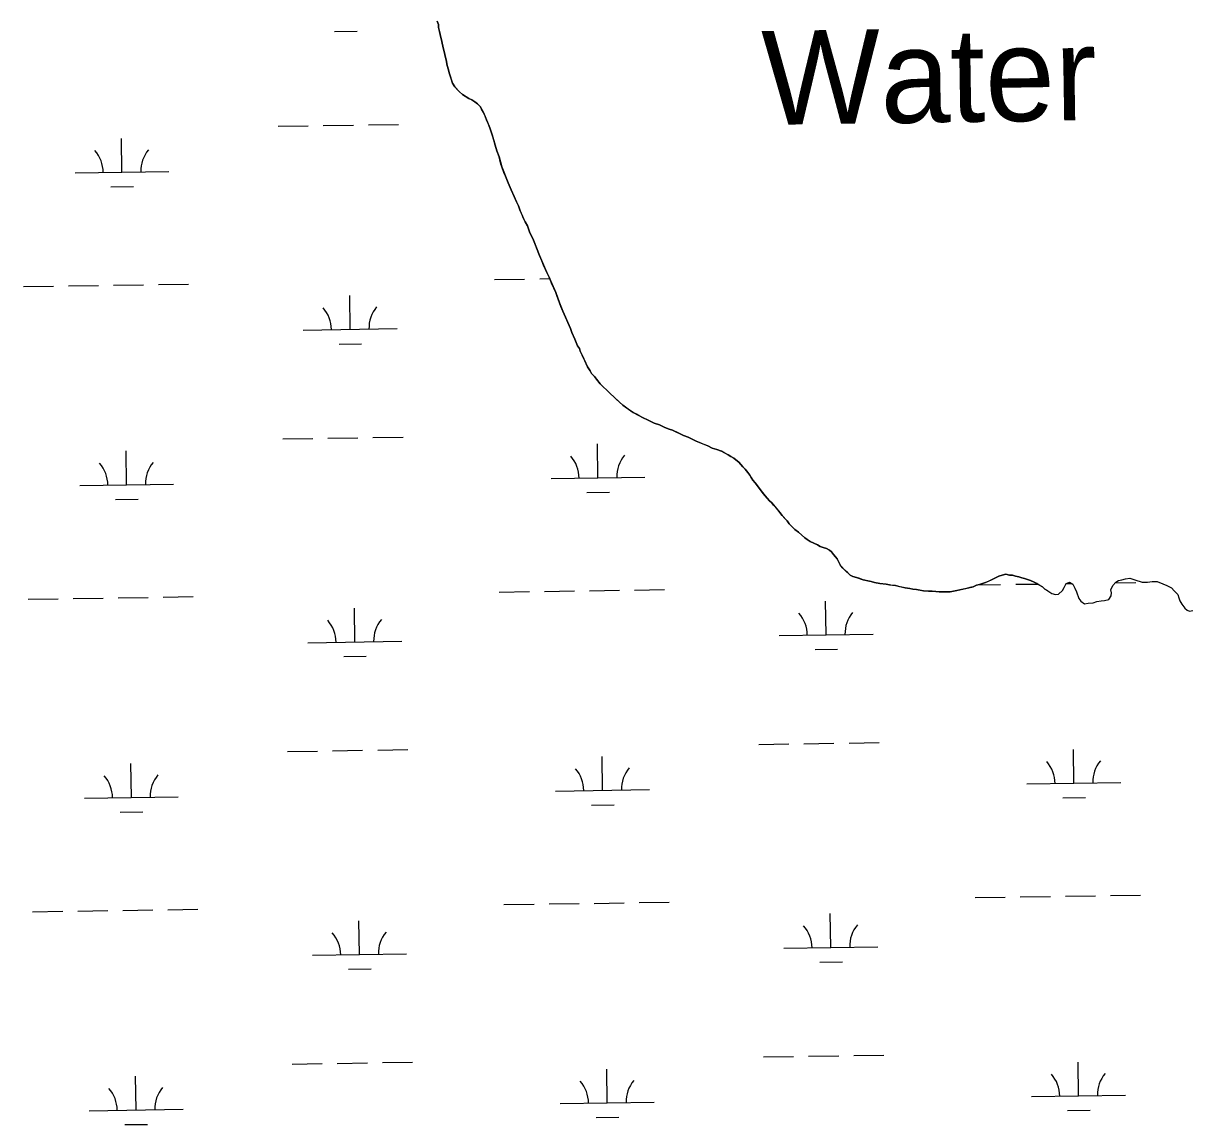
# Model space of a CAD drawing. Extents: x 3807117 to 3845308, y 337856 to 363736.
# Drawn here: x 3840561 to 3841805, y 350277 to 351449 of the extents above; entities that cross this region are included whole.
import ezdxf

# ---------------------------------------------------------------- set-up
doc = ezdxf.new("R2010")
doc.units = 0
for name, color, linetype in [('V-RIVR-IDEN', 7, 'Continuous'), ('V-TOPO-SHOR', 7, 'Continuous'), ('V-WETL-SWMP', 7, 'Continuous')]:
    doc.layers.add(name, color=color, linetype=linetype)

msp = doc.modelspace()

# ---------------------------------------------------------------- linework, layer by layer
at = {"layer": 'V-TOPO-SHOR'}
for p, q in [((3841668.1, 350845.4), (3841670, 350848.6)), ((3841670, 350848.6), (3841672, 350852.6)), ((3841672, 350852.6), (3841675.5, 350854.2)), ((3841675.5, 350854.2), (3841679.1, 350852.2)), ((3841679.1, 350852.2), (3841681.1, 350847.9)), ((3841681.1, 350847.9), (3841683.1, 350844)), ((3841719.6, 350845.9), (3841721.5, 350850.7)), ((3841721.5, 350850.7), (3841724.7, 350854.2)), ((3841724.7, 350854.2), (3841727.8, 350855.9)), ((3841727.8, 350855.9), (3841731.4, 350856.7)), ((3841731.4, 350856.7), (3841735.3, 350857.9)), ((3841735.3, 350857.9), (3841739.7, 350858.3)), ((3841739.7, 350858.3), (3841744.9, 350856.8)), ((3841744.9, 350856.8), (3841752.8, 350854.1)), ((3841752.8, 350854.1), (3841758.4, 350854.2)), ((3841758.4, 350854.2), (3841763.5, 350855)), ((3841763.5, 350855), (3841768.7, 350855)), ((3841768.7, 350855), (3841775, 350852.3)), ((3841775, 350852.3), (3841779, 350850.8)), ((3841779, 350850.8), (3841784.2, 350848)), ((3841784.2, 350848), (3841787, 350844.9)), ((3841651.5, 350845.6), (3841652.6, 350844.9)), ((3841652.6, 350844.9), (3841656.6, 350842.1)), ((3841656.6, 350842.1), (3841660.6, 350841)), ((3841660.6, 350841), (3841663.7, 350841.4)), ((3841663.7, 350841.4), (3841668.1, 350845.4)), ((3841683.1, 350844), (3841685.6, 350836.8)), ((3841685.6, 350836.8), (3841687.6, 350834.1)), ((3841687.6, 350834.1), (3841691.6, 350831)), ((3841704.6, 350833.5), (3841709.4, 350834.3)), ((3841709.4, 350834.3), (3841712.6, 350834.7)), ((3841712.6, 350834.7), (3841717.3, 350835.9)), ((3841717.3, 350835.9), (3841719.7, 350839.5)), ((3841720.4, 350842.7), (3841719.6, 350845.9)), ((3841719.7, 350839.5), (3841720.4, 350842.7)), ((3841787, 350844.9), (3841791, 350841)), ((3841791, 350841), (3841791.8, 350837.4)), ((3841791.8, 350837.4), (3841793, 350834.3)), ((3841793, 350834.3), (3841795.1, 350830.7)), ((3841691.6, 350831), (3841695.5, 350831.8)), ((3841695.5, 350831.8), (3841700.7, 350832.2)), ((3841700.7, 350832.2), (3841704.6, 350833.5)), ((3841795.1, 350830.7), (3841798.3, 350826.4)), ((3841798.3, 350826.4), (3841800.7, 350824.4)), ((3841800.7, 350824.4), (3841803.4, 350823.3)), ((3841803.4, 350823.3), (3841807, 350824.1))]:
    msp.add_line(p, q, dxfattribs=at)
for points in [[(3841058.4, 351337.6), (3841056.3, 351342.3), (3841054.7, 351346.3), (3841053.1, 351350.2), (3841051.5, 351354.1), (3841049.5, 351357.6), (3841047.9, 351360.4), (3841045.1, 351363.1), (3841042.4, 351365.4), (3841039.2, 351367.4), (3841035.7, 351368.9), (3841032.9, 351370.8), (3841029.3, 351373.2), (3841025.8, 351375.9), (3841023.8, 351378.2), (3841021, 351381.3), (3841018.6, 351385.3), (3841017, 351390), (3841015.4, 351395.1), (3841013.7, 351400.5), (3841012.5, 351405.6), (3841012.1, 351408.8), (3841010.9, 351412.7), (3841009.6, 351419), (3841008.4, 351422.9), (3841007.2, 351429.6), (3841005.2, 351437), (3841004.7, 351440.2), (3841003.5, 351444.5), (3841003.5, 351447.6), (3841002.3, 351451.2)], [(3841336.6, 350965.5), (3841335, 350968.2), (3841333, 350970.9), (3841330.2, 350974.4), (3841327.8, 350976.8), (3841325.4, 350979.5), (3841323.5, 350981.9), (3841320.3, 350984.2), (3841317.9, 350986.1), (3841314.7, 350988.1), (3841312, 350989.6), (3841308.4, 350991.6), (3841304.9, 350993.5), (3841300.1, 350995.4), (3841295, 350996.9), (3841290.3, 350999.2), (3841285.5, 351001.2), (3841281.6, 351002.7), (3841278, 351004.2), (3841272.9, 351006.6), (3841269.3, 351008.5), (3841264.6, 351010.4), (3841258.7, 351013.1), (3841252.8, 351015.8), (3841249.2, 351017), (3841244.5, 351018.9), (3841238.9, 351021.6), (3841233.4, 351023.5), (3841229.1, 351025.4), (3841226.3, 351027), (3841221.6, 351028.9), (3841218, 351030.8), (3841214.5, 351032.8), (3841210.9, 351034.7), (3841208.1, 351036.6), (3841204.2, 351039.4), (3841199.8, 351042.5), (3841196.3, 351045.6), (3841193.1, 351048.7), (3841190.7, 351051), (3841186.3, 351054.9), (3841183.2, 351058), (3841178.4, 351062.3), (3841175.6, 351065.1), (3841171.7, 351070.1), (3841169.7, 351072.9), (3841166.5, 351076.4), (3841164.9, 351079.1), (3841162.1, 351083.4), (3841159.3, 351089.7), (3841156.5, 351095.9), (3841154.5, 351099.9), (3841153.7, 351103), (3841151.7, 351105.7), (3841148.9, 351112.8), (3841145.7, 351119.8), (3841144, 351124.1), (3841141.2, 351130.4), (3841138.8, 351136.3), (3841136, 351142.5), (3841134, 351147.6), (3841132.4, 351151.6), (3841129.6, 351159.4), (3841128.4, 351162.5), (3841126.4, 351167.2), (3841124.7, 351170.7), (3841122.7, 351175.4), (3841121.5, 351178.6), (3841119.1, 351183.7), (3841117.5, 351186.8), (3841115.5, 351191.5), (3841113.5, 351196.2), (3841111.1, 351201.7), (3841107.9, 351209.9), (3841106.7, 351213), (3841104.7, 351218.1), (3841102.6, 351222.8), (3841101, 351226), (3841099.4, 351230.3), (3841098.2, 351233.4), (3841095.8, 351237.7), (3841094.2, 351241.2), (3841092.2, 351245.9), (3841090.6, 351249.5), (3841088.6, 351254.6), (3841086.6, 351258.9), (3841084.2, 351264.7), (3841081, 351271.8), (3841077.8, 351279.2), (3841074.9, 351286.3), (3841073.3, 351290.2), (3841070.9, 351296.1), (3841070.1, 351299.2), (3841068.9, 351303.5), (3841068.1, 351306.7), (3841065.7, 351313.3), (3841064, 351319.2), (3841062.4, 351324.7), (3841060.8, 351330.2), (3841059.2, 351334.5), (3841058.4, 351337.6)], [(3841652.6, 350844.9), (3841649.4, 350846.8), (3841646.7, 350849.1), (3841643.9, 350850.7), (3841640.7, 350852.6), (3841638, 350854.2), (3841634, 350856.1), (3841630.9, 350856.9), (3841627.7, 350858), (3841624.6, 350858.8), (3841621.4, 350859.9), (3841617.9, 350860.7), (3841614.7, 350861.8), (3841611.6, 350861.8), (3841607.6, 350862.6), (3841603.7, 350861.7), (3841600.2, 350860.5), (3841596.7, 350858.9), (3841593.1, 350856.9), (3841589.6, 350855.3), (3841586.1, 350853.7), (3841582.9, 350852.9), (3841579.8, 350851.7), (3841576.3, 350850.9), (3841572.8, 350849.3), (3841569.2, 350848.4), (3841565.7, 350847.6), (3841562.2, 350846.8), (3841558.6, 350846), (3841555.5, 350845.2), (3841552, 350844.7), (3841548.4, 350843.9), (3841544.1, 350843.9), (3841541, 350843.9), (3841536.6, 350843.8), (3841533.1, 350844.2), (3841529.2, 350844.5), (3841525.2, 350844.5), (3841520.1, 350844.8), (3841516.2, 350845.6), (3841512.6, 350846.4), (3841508.7, 350846.7), (3841505.5, 350847.5), (3841500.4, 350848.2), (3841496.9, 350849), (3841493.7, 350849.7), (3841490.2, 350850.5), (3841487, 350850.8), (3841483.9, 350851.2), (3841480.3, 350852), (3841476.8, 350852.3), (3841473.6, 350852.7), (3841467.7, 350853.8), (3841464.2, 350855), (3841460.6, 350855.7), (3841455.9, 350856.8), (3841452.4, 350858), (3841448.8, 350859.1), (3841444.9, 350860.3), (3841442.1, 350861.8), (3841439.3, 350864.2), (3841436.6, 350866.5), (3841434.2, 350869.2), (3841431.8, 350872), (3841429.8, 350875.5), (3841428.2, 350879), (3841426.2, 350881.3), (3841424.2, 350883.7), (3841422.2, 350886.4), (3841419.8, 350888.4), (3841416.7, 350889.9), (3841413.1, 350891.1), (3841410, 350892.2), (3841407.2, 350893.8), (3841403.3, 350895.7), (3841399.3, 350897.6), (3841396.1, 350899.6), (3841393.8, 350901.5), (3841390.6, 350904.2), (3841387, 350907.3), (3841383.1, 350910.4), (3841380.3, 350913.2), (3841377.1, 350916.3), (3841374.7, 350919.4), (3841372.4, 350922.1), (3841369.6, 350925.3), (3841367.2, 350928.4), (3841365.2, 350930.7), (3841362.8, 350933.5), (3841360.4, 350936.2), (3841358.4, 350938.5), (3841356.1, 350940.9), (3841353.7, 350943.6), (3841351.3, 350945.9), (3841349.3, 350948.7), (3841347.3, 350951.4), (3841345.3, 350953.7), (3841342.9, 350956.9), (3841340.6, 350960), (3841338.2, 350962.7), (3841336.6, 350965.5)]]:
    msp.add_lwpolyline(points, dxfattribs=at)
at = {"layer": 'V-WETL-SWMP'}
for p, q in [((3840892.8, 351440.2), (3840916.8, 351440.6)), ((3840832.9, 351339.3), (3840864.9, 351339.8)), ((3840880.9, 351340.1), (3840912.9, 351340.5)), ((3840928.9, 351340.8), (3840960.9, 351341.3)), ((3840666.5, 351290.4), (3840666, 351326.4)), ((3840616.5, 351289.7), (3840716.5, 351291.2)), ((3840654.7, 351274.8), (3840678.7, 351275.2)), ((3840609.5, 351169.5), (3840641.5, 351169.9)), ((3840657.5, 351170.2), (3840689.5, 351170.7)), ((3840705.5, 351170.9), (3840737.5, 351171.4)), ((3841063.3, 351176.3), (3841095.3, 351176.7)), ((3841111.3, 351177), (3841122.1, 351177.2)), ((3840561.5, 351168.8), (3840593.5, 351169.2)), ((3840909.5, 351123.2), (3840909, 351159.2)), ((3840859.5, 351122.5), (3840959.5, 351124)), ((3840897.8, 351107.6), (3840921.7, 351108)), ((3840885.8, 351007.4), (3840917.8, 351007.9)), ((3840933.8, 351008.1), (3840965.8, 351008.6)), ((3840837.8, 351006.7), (3840869.8, 351007.2)), ((3841173.4, 350965.3), (3841172.8, 351001.3)), ((3840671.5, 350957.8), (3840671, 350993.8)), ((3840621.5, 350957), (3840721.5, 350958.5)), ((3841123.4, 350964.5), (3841223.3, 350966)), ((3841161.6, 350949.7), (3841185.6, 350950)), ((3840659.7, 350942.2), (3840683.7, 350942.5)), ((3841212.3, 350845.8), (3841244.3, 350846.3)), ((3841578, 350851.3), (3841602.2, 350851.6)), ((3841618.2, 350851.9), (3841641.4, 350852.2)), ((3841672.2, 350852.7), (3841678.1, 350852.8)), ((3841724, 350853.5), (3841746.1, 350853.8)), ((3840566.5, 350836.1), (3840598.5, 350836.6)), ((3840614.5, 350836.8), (3840646.5, 350837.3)), ((3840662.5, 350837.6), (3840694.5, 350838)), ((3840710.4, 350838.3), (3840742.4, 350838.8)), ((3841068.3, 350843.6), (3841100.3, 350844.1)), ((3841116.3, 350844.4), (3841148.3, 350844.8)), ((3841164.3, 350845.1), (3841196.3, 350845.6)), ((3841416.4, 350798.1), (3841415.8, 350834.1)), ((3840914.5, 350790.6), (3840914, 350826.6)), ((3841366.4, 350797.4), (3841466.3, 350798.8)), ((3840864.5, 350789.8), (3840964.5, 350791.3)), ((3840902.7, 350775), (3840926.7, 350775.3)), ((3841404.6, 350782.5), (3841428.6, 350782.8)), ((3840842.8, 350674.1), (3840874.8, 350674.5)), ((3840890.8, 350674.8), (3840922.8, 350675.3)), ((3840938.8, 350675.5), (3840970.8, 350676)), ((3841344.7, 350681.6), (3841376.7, 350682.1)), ((3841392.7, 350682.3), (3841424.7, 350682.8)), ((3841440.7, 350683), (3841472.7, 350683.5)), ((3841680.2, 350640.2), (3841679.6, 350676.2)), ((3840676.5, 350625.1), (3840675.9, 350661.1)), ((3841178.3, 350632.7), (3841177.8, 350668.6)), ((3841630.2, 350639.4), (3841730.2, 350640.9)), ((3840626.5, 350624.4), (3840726.5, 350625.9)), ((3841128.3, 350631.9), (3841228.3, 350633.4)), ((3841668.4, 350624.6), (3841692.4, 350624.9)), ((3841166.6, 350617), (3841190.6, 350617.4)), ((3840664.7, 350609.5), (3840688.7, 350609.9)), ((3841073.3, 350511), (3841105.3, 350511.5)), ((3841121.3, 350511.7), (3841153.3, 350512.2)), ((3841169.3, 350512.4), (3841201.3, 350512.9)), ((3841217.3, 350513.2), (3841249.3, 350513.6)), ((3841575.2, 350518.5), (3841607.1, 350519)), ((3841623.1, 350519.2), (3841655.1, 350519.7)), ((3841671.1, 350520), (3841703.1, 350520.4)), ((3841719.1, 350520.7), (3841751.1, 350521.2)), ((3840571.4, 350503.5), (3840603.4, 350504)), ((3840619.4, 350504.2), (3840651.4, 350504.7)), ((3840667.4, 350504.9), (3840699.4, 350505.4)), ((3840715.4, 350505.6), (3840747.4, 350506.1)), ((3841421.3, 350465.5), (3841420.8, 350501.5)), ((3840919.5, 350457.9), (3840918.9, 350493.9)), ((3841371.3, 350464.7), (3841471.3, 350466.2)), ((3840869.5, 350457.2), (3840969.5, 350458.7)), ((3841409.6, 350449.9), (3841433.6, 350450.2)), ((3840907.7, 350442.3), (3840931.7, 350442.7)), ((3841349.7, 350348.9), (3841381.7, 350349.4)), ((3841397.7, 350349.7), (3841429.7, 350350.1)), ((3841445.7, 350350.4), (3841477.7, 350350.9)), ((3840847.8, 350341.4), (3840879.8, 350341.9)), ((3840895.8, 350342.1), (3840927.8, 350342.6)), ((3840943.8, 350342.9), (3840975.8, 350343.3)), ((3841685.2, 350307.5), (3841684.6, 350343.5)), ((3840681.5, 350292.5), (3840680.9, 350328.5)), ((3841183.3, 350300), (3841182.8, 350336)), ((3841133.3, 350299.3), (3841233.3, 350300.8)), ((3841635.2, 350306.8), (3841735.2, 350308.3)), ((3840631.5, 350291.7), (3840731.5, 350293.2)), ((3841673.4, 350291.9), (3841697.4, 350292.3)), ((3840669.7, 350276.9), (3840693.7, 350277.2)), ((3841171.6, 350284.4), (3841195.5, 350284.8))]:
    msp.add_line(p, q, dxfattribs=at)
for points in [[(3841002.3, 351451.2), (3841003.5, 351447.6), (3841003.5, 351444.5), (3841004.7, 351440.2), (3841005.2, 351437), (3841007.2, 351429.6), (3841008.4, 351422.9), (3841009.6, 351419), (3841010.9, 351412.7), (3841012.1, 351408.8), (3841012.5, 351405.6), (3841013.7, 351400.5), (3841015.4, 351395.1), (3841018.6, 351385.3), (3841021, 351381.3), (3841025.8, 351375.9), (3841029.3, 351373.2), (3841035.7, 351368.9), (3841039.2, 351367.4), (3841042.4, 351365.4), (3841045.1, 351363.1), (3841047.9, 351360.4), (3841051.5, 351354.1), (3841058.4, 351337.6), (3841059.2, 351334.5), (3841060.8, 351330.2), (3841064, 351319.2), (3841065.7, 351313.3), (3841068.1, 351306.7), (3841070.9, 351296.1), (3841077.8, 351279.2), (3841081, 351271.8), (3841084.2, 351264.7), (3841086.6, 351258.9), (3841088.6, 351254.6), (3841090.6, 351249.5), (3841094.2, 351241.2), (3841095.8, 351237.7), (3841098.2, 351233.4), (3841101, 351226), (3841102.6, 351222.8), (3841104.7, 351218.1), (3841111.1, 351201.7), (3841117.5, 351186.8), (3841119.1, 351183.7), (3841121.5, 351178.6), (3841122.7, 351175.4), (3841128.4, 351162.5), (3841132.4, 351151.6), (3841136, 351142.5), (3841138.8, 351136.3), (3841141.2, 351130.4), (3841144, 351124.1), (3841145.7, 351119.8), (3841148.9, 351112.8), (3841151.7, 351105.7), (3841153.7, 351103), (3841154.5, 351099.9), (3841156.5, 351095.9), (3841162.1, 351083.4), (3841164.9, 351079.1), (3841166.5, 351076.4), (3841169.7, 351072.9)], [(3841169.7, 351072.9), (3841171.7, 351070.1), (3841175.6, 351065.1), (3841178.4, 351062.3), (3841183.2, 351058), (3841186.3, 351054.9), (3841190.7, 351051), (3841196.3, 351045.6), (3841199.8, 351042.5), (3841210.9, 351034.7), (3841221.6, 351028.9), (3841226.3, 351027), (3841229.1, 351025.4), (3841233.4, 351023.5), (3841238.9, 351021.6), (3841244.5, 351018.9), (3841249.2, 351017), (3841252.8, 351015.8), (3841264.6, 351010.4), (3841269.3, 351008.5), (3841272.9, 351006.6), (3841278, 351004.2), (3841281.6, 351002.7), (3841290.3, 350999.2), (3841295, 350996.9), (3841300.1, 350995.4), (3841304.9, 350993.5), (3841312, 350989.6), (3841314.7, 350988.1), (3841317.9, 350986.1), (3841320.3, 350984.2), (3841323.4, 350981.9), (3841327.8, 350976.8), (3841330.2, 350974.4), (3841333, 350970.9), (3841335, 350968.2), (3841336.6, 350965.5), (3841338.2, 350962.7), (3841340.6, 350960), (3841345.3, 350953.7), (3841347.3, 350951.4), (3841351.3, 350945.9), (3841353.7, 350943.6), (3841356.1, 350940.9), (3841358.4, 350938.5), (3841367.2, 350928.4), (3841369.6, 350925.3), (3841374.7, 350919.4), (3841377.1, 350916.3), (3841383.1, 350910.4), (3841387, 350907.3), (3841393.8, 350901.5), (3841396.1, 350899.6), (3841399.3, 350897.6), (3841407.2, 350893.8), (3841410, 350892.2), (3841413.1, 350891.1), (3841416.7, 350889.9), (3841419.8, 350888.4), (3841422.2, 350886.4), (3841424.2, 350883.7), (3841428.2, 350879), (3841429.8, 350875.5), (3841431.8, 350872), (3841436.6, 350866.5), (3841442.1, 350861.8), (3841444.9, 350860.3), (3841448.8, 350859.1), (3841455.9, 350856.8), (3841464.2, 350855), (3841467.7, 350853.8), (3841473.6, 350852.7), (3841480.3, 350852), (3841483.9, 350851.2), (3841490.2, 350850.5), (3841500.4, 350848.2), (3841505.5, 350847.5), (3841508.7, 350846.7), (3841512.6, 350846.4), (3841520.1, 350844.8), (3841525.2, 350844.5), (3841529.2, 350844.5), (3841536.6, 350843.8), (3841548.4, 350843.9), (3841552, 350844.7), (3841555.5, 350845.2), (3841558.6, 350846), (3841572.8, 350849.3), (3841576.3, 350850.9), (3841579.8, 350851.7), (3841582.9, 350852.9), (3841586.1, 350853.7), (3841593.1, 350856.9), (3841596.7, 350858.9), (3841600.2, 350860.5), (3841603.7, 350861.7), (3841607.6, 350862.6), (3841611.6, 350861.8), (3841614.7, 350861.8), (3841617.9, 350860.7), (3841621.4, 350859.9)], [(3841621.4, 350859.9), (3841624.6, 350858.8), (3841627.7, 350858), (3841630.9, 350856.9), (3841634, 350856.1), (3841638, 350854.2), (3841646.7, 350849.1), (3841649.4, 350846.8), (3841652.6, 350844.9), (3841656.6, 350842.1), (3841660.6, 350841), (3841663.7, 350841.4), (3841668.1, 350845.4), (3841670, 350848.6), (3841672, 350852.6), (3841675.5, 350854.2), (3841679.1, 350852.2), (3841681.1, 350847.9), (3841683.1, 350844), (3841685.6, 350836.8), (3841687.6, 350834.1), (3841691.6, 350831), (3841695.5, 350831.8), (3841700.7, 350832.2), (3841704.6, 350833.5), (3841709.4, 350834.3), (3841712.6, 350834.7), (3841717.3, 350835.9), (3841719.7, 350839.5), (3841720.4, 350842.7), (3841719.6, 350845.9), (3841721.5, 350850.7), (3841724.7, 350854.2), (3841727.8, 350855.9), (3841731.4, 350856.7), (3841735.3, 350857.9), (3841739.7, 350858.3), (3841744.9, 350856.8), (3841752.8, 350854.1), (3841758.4, 350854.2), (3841763.5, 350855), (3841768.7, 350855), (3841775, 350852.3), (3841779, 350850.8), (3841784.2, 350848), (3841787, 350844.9), (3841791, 350841), (3841791.8, 350837.4), (3841793, 350834.3), (3841795.1, 350830.7), (3841798.3, 350826.4), (3841800.7, 350824.4), (3841803.4, 350823.3), (3841807, 350824.1)]]:
    msp.add_lwpolyline(points, dxfattribs=at)
for centre, start, end in [((3840611.3, 351290.1), 0.0865, 41.6302), ((3840721.7, 351291.7), 140.0865, 181.6302), ((3840854.3, 351122.9), 0.0865, 41.6302), ((3840964.7, 351124.5), 140.0865, 181.6302), ((3841118.1, 350964.9), 0.0865, 41.6302), ((3841228.6, 350966.6), 140.0865, 181.6302), ((3840616.3, 350957.4), 0.0865, 41.6302), ((3840726.7, 350959.1), 140.0865, 181.6302), ((3841471.6, 350799.4), 140.0865, 181.6302), ((3840859.3, 350790.2), 0.0865, 41.6302), ((3840969.7, 350791.9), 140.0865, 181.6302), ((3841361.1, 350797.7), 0.0865, 41.6302), ((3841624.9, 350639.8), 0.0865, 41.6302), ((3841735.4, 350641.5), 140.0865, 181.6302), ((3840621.2, 350624.8), 0.0865, 41.6302), ((3840731.7, 350626.4), 140.0865, 181.6302), ((3841123.1, 350632.3), 0.0865, 41.6302), ((3841233.6, 350634), 140.0865, 181.6302), ((3841366.1, 350465.1), 0.0865, 41.6302), ((3841476.6, 350466.8), 140.0865, 181.6302), ((3840864.2, 350457.6), 0.0865, 41.6302), ((3840974.7, 350459.2), 140.0865, 181.6302), ((3841629.9, 350307.2), 0.0865, 41.6302), ((3841740.4, 350308.8), 140.0865, 181.6302), ((3840626.2, 350292.1), 0.0865, 41.6302), ((3840736.7, 350293.8), 140.0865, 181.6302), ((3841128.1, 350299.7), 0.0865, 41.6302), ((3841238.5, 350301.3), 140.0865, 181.6302)]:
    msp.add_arc(centre, 35.2, start, end, dxfattribs=at)

# ---------------------------------------------------------------- texts
at = {"layer": 'V-RIVR-IDEN'}
msp.add_text('Water', height=100, rotation=0.8756, dxfattribs=at).set_placement((3841348.5, 351340.7))

doc.saveas('drawing.dxf')
